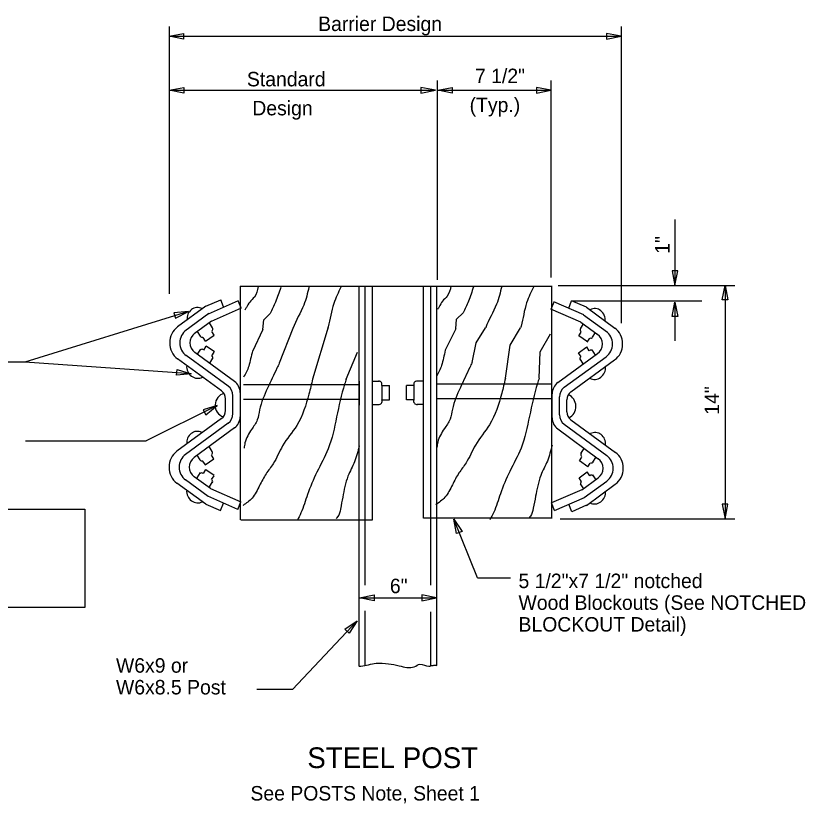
# Model space of a CAD drawing. Extents: x -0.7 to 88.8, y -25.9 to 22.
# Drawn here: x 69.51 to 77.13, y -13.93 to -6.32 of the extents above; entities that cross this region are included whole.
import ezdxf

# ---------------------------------------------------------------- set-up
doc = ezdxf.new("R2010")
doc.units = 0
doc.layers.add('Default', color=7, linetype='Continuous')

msp = doc.modelspace()

# ---------------------------------------------------------------- linework, layer by layer
at = {"layer": 'Default'}
for p, q in [((70.9916, -6.4238), (70.9917, -9.0079)), ((75.3554, -6.4238), (75.3554, -9.2896)), ((70.9896, -6.5183), (75.3554, -6.5183)), ((73.58, -6.9458), (73.58, -8.8721)), ((74.6788, -6.9458), (74.6788, -8.8479)), ((70.9913, -7.0403), (71.5695, -7.0403)), ((71.5695, -7.0403), (73.5629, -7.0403)), ((73.5856, -7.0403), (73.9534, -7.0403)), ((73.9534, -7.0403), (74.6788, -7.0403)), ((75.8756, -8.2897), (75.8756, -8.9251)), ((71.6781, -8.9328), (74.6891, -8.9328)), ((71.6781, -8.9328), (71.6781, -11.1893)), ((72.8268, -11.1891), (72.8268, -8.9399)), ((72.8835, -11.1891), (72.8835, -8.9399)), ((72.9543, -11.1891), (72.9543, -8.9399)), ((73.4472, -11.1748), (73.4472, -8.9353)), ((73.5181, -11.1748), (73.5181, -8.9353)), ((73.5747, -11.1748), (73.5747, -8.9353)), ((74.6848, -8.9328), (74.6848, -11.1749)), ((74.7482, -8.9251), (76.4542, -8.9251)), ((76.3597, -8.9251), (76.3597, -9.6308)), ((71.3455, -9.1263), (71.4894, -9.0634)), ((71.5169, -9.1336), (71.4899, -9.0643)), ((71.3457, -9.1266), (71.0728, -9.3266)), ((71.3702, -9.1993), (71.6596, -9.0729)), ((71.3994, -9.2698), (71.689, -9.1436)), ((71.6858, -9.1431), (71.6588, -9.0739)), ((74.681, -9.1539), (74.708, -9.0846)), ((74.9966, -9.2101), (74.7071, -9.0838)), ((74.85, -9.1443), (74.877, -9.0751)), ((74.8774, -9.0743), (76.1356, -9.0743)), ((75.0214, -9.1371), (74.8774, -9.0743)), ((75.0211, -9.1374), (75.294, -9.3374)), ((75.8756, -9.087), (75.8756, -9.462)), ((71.3727, -9.1978), (71.1427, -9.3664)), ((71.9674, -9.1984), (71.9051, -9.2591)), ((73.8296, -9.1913), (73.7673, -9.2519)), ((74.9674, -9.2806), (74.6779, -9.1543)), ((74.9941, -9.2086), (75.2241, -9.3773)), ((71.3986, -9.2703), (71.2319, -9.3924)), ((71.41, -9.3349), (71.3798, -9.2876)), ((71.8969, -9.3531), (71.9051, -9.2591)), ((73.7591, -9.3459), (73.7673, -9.2519)), ((74.9626, -9.3436), (74.9927, -9.2963)), ((74.9683, -9.2811), (75.135, -9.4033)), ((71.2942, -9.4174), (71.2651, -9.3718)), ((71.4251, -9.4049), (71.4025, -9.3694)), ((71.8969, -9.3531), (71.7947, -9.5639)), ((72.1865, -9.3413), (72.0544, -9.6771)), ((72.5267, -9.3281), (72.3761, -9.8301)), ((73.7591, -9.3459), (73.6581, -9.5521)), ((71.3429, -9.4639), (71.3198, -9.4276)), ((71.3427, -9.4634), (71.4253, -9.4049)), ((75.0299, -9.4721), (74.9473, -9.4134)), ((74.9474, -9.4136), (74.9701, -9.3781)), ((75.0296, -9.4724), (75.0528, -9.4363)), ((75.0784, -9.4261), (75.1075, -9.3804)), ((71.3245, -9.5498), (71.3491, -9.5111)), ((71.4276, -9.5688), (71.349, -9.5113)), ((74.945, -9.5774), (75.0236, -9.5199)), ((75.0481, -9.5584), (75.0234, -9.5198)), ((71.5596, -9.8986), (71.1556, -9.6041)), ((71.6227, -9.8536), (71.2381, -9.5733)), ((71.2646, -9.5901), (71.2962, -9.5401)), ((71.4035, -9.6073), (71.4273, -9.5698)), ((72.7019, -9.8301), (72.8103, -9.5713)), ((74.7441, -9.8643), (75.1287, -9.5839)), ((74.9691, -9.6159), (74.9452, -9.5783)), ((75.1081, -9.5988), (75.0763, -9.5488)), ((71.2038, -9.7793), (69.5972, -9.6669)), ((71.4964, -9.9436), (71.0732, -9.6351)), ((71.3826, -9.6761), (71.4136, -9.6276)), ((74.8072, -9.9093), (75.2111, -9.6149)), ((74.8705, -9.9543), (75.2936, -9.6459)), ((74.99, -9.6848), (74.9591, -9.6361)), ((76.3597, -9.6308), (76.3597, -11.1798)), ((72.8223, -9.8877), (71.7103, -9.8877)), ((72.8282, -10.0842), (72.8282, -9.8517)), ((72.9528, -9.8504), (73.0212, -9.8504)), ((73.0451, -9.8912), (73.1177, -9.8912)), ((73.0451, -9.8912), (73.0461, -10.0314)), ((73.1177, -10.0314), (73.1177, -9.8912)), ((73.2824, -10.0314), (73.2824, -9.8922)), ((73.3551, -9.8912), (73.2834, -9.8912)), ((73.3551, -9.8912), (73.3541, -10.0314)), ((73.4473, -9.8504), (73.379, -9.8504)), ((74.6845, -9.8807), (73.5726, -9.8807)), ((74.6905, -10.2049), (74.6905, -9.9724)), ((71.5347, -10.1351), (71.5347, -10.0208)), ((71.6056, -10.1644), (71.6056, -9.9913)), ((72.8223, -10.0279), (71.71, -10.0279)), ((73.0461, -10.0314), (73.1177, -10.0314)), ((73.3541, -10.0314), (73.2824, -10.0314)), ((74.6845, -10.0209), (73.5721, -10.0209)), ((74.7612, -10.1753), (74.7612, -10.0021)), ((74.8321, -10.1459), (74.8321, -10.0314)), ((71.455, -10.0859), (70.7698, -10.4277)), ((71.6056, -10.0833), (71.6056, -10.0724)), ((72.9528, -10.0749), (73.0124, -10.0749)), ((73.4473, -10.0749), (73.3877, -10.0749)), ((74.7612, -10.0939), (74.7612, -10.0833)), ((71.4966, -10.2123), (71.0662, -10.5276)), ((71.5597, -10.2569), (71.1486, -10.5584)), ((74.8071, -10.2678), (75.2181, -10.5693)), ((74.8702, -10.2229), (75.3006, -10.5384)), ((71.6231, -10.3019), (71.2313, -10.5891)), ((74.7438, -10.3128), (75.1356, -10.5999)), ((69.6048, -10.4277), (70.7698, -10.4277)), ((71.4076, -10.5296), (71.3775, -10.4823)), ((74.9683, -10.5501), (74.9984, -10.5028)), ((71.2918, -10.6123), (71.2627, -10.5666)), ((71.4228, -10.5998), (71.4001, -10.5643)), ((74.9531, -10.6203), (74.9757, -10.5848)), ((75.0841, -10.6328), (75.1131, -10.5871)), ((71.3406, -10.6586), (71.3174, -10.6223)), ((71.3404, -10.6583), (71.4229, -10.5996)), ((75.0356, -10.6788), (74.953, -10.6201)), ((75.0353, -10.6791), (75.0585, -10.6428)), ((71.2621, -10.7848), (71.2939, -10.7348)), ((71.3221, -10.7444), (71.3468, -10.7058)), ((71.4253, -10.7634), (71.3466, -10.7059)), ((74.9506, -10.7839), (75.0293, -10.7264)), ((75.0537, -10.7649), (75.0291, -10.7263)), ((71.3668, -10.9639), (71.1491, -10.8053)), ((71.3889, -10.8889), (71.2315, -10.7743)), ((71.3802, -10.8709), (71.4112, -10.8223)), ((71.4011, -10.8019), (71.425, -10.7644)), ((74.9748, -10.8224), (74.9509, -10.7849)), ((74.9779, -10.8998), (75.1353, -10.7851)), ((75, -10.9748), (75.2178, -10.8161)), ((75.1137, -10.8053), (75.082, -10.7553)), ((71.3461, -11.0399), (71.0666, -10.8363)), ((71.3889, -10.8886), (71.6826, -11.0166)), ((74.9779, -10.8994), (74.6842, -11.0274)), ((74.9956, -10.8914), (74.9647, -10.8428)), ((75.0208, -11.0508), (75.3002, -10.8471)), ((71.6546, -11.0898), (71.3652, -10.9634)), ((74.7121, -11.1006), (75.0016, -10.9743)), ((71.3437, -11.0391), (71.4877, -11.1019)), ((71.4868, -11.1016), (71.5151, -11.0289)), ((71.6538, -11.0898), (71.6826, -11.0161)), ((74.713, -11.1006), (74.6843, -11.0269)), ((74.88, -11.1123), (74.8516, -11.0398)), ((75.0231, -11.0499), (74.8791, -11.1126)), ((71.6831, -11.1891), (72.9543, -11.1891)), ((72.8268, -12.6013), (72.8268, -11.1891)), ((72.8835, -11.8228), (72.8835, -11.1891)), ((74.6891, -11.1748), (73.4472, -11.1748)), ((73.5181, -11.8206), (73.5181, -11.1748)), ((73.5747, -12.5966), (73.5747, -11.1748)), ((73.9682, -11.7506), (73.7412, -11.1828)), ((74.7661, -11.1798), (76.4542, -11.1798)), ((73.9682, -11.7506), (74.2891, -11.7506)), ((72.8268, -11.9441), (73.572, -11.9441)), ((72.8305, -11.9441), (73.018, -11.9441)), ((72.8835, -12.6013), (72.8835, -12.0703)), ((73.5181, -12.5966), (73.5181, -12.0789)), ((72.1817, -12.8304), (72.8061, -12.1656)), ((72.1817, -12.8304), (71.839, -12.8304))]:
    msp.add_line(p, q, dxfattribs=at)
for points in [[(71.1296, -6.5463), (70.9896, -6.5183), (71.1296, -6.4903)], [(75.2154, -6.5463), (75.3554, -6.5183), (75.2154, -6.4903)], [(71.1313, -7.0683), (70.9913, -7.0403), (71.1313, -7.0123)], [(73.4229, -7.0683), (73.5629, -7.0403), (73.4229, -7.0123)], [(73.7256, -7.0683), (73.5856, -7.0403), (73.7256, -7.0123)], [(74.5388, -7.0683), (74.6788, -7.0403), (74.5388, -7.0123)], [(75.8476, -8.7851), (75.8756, -8.9251), (75.9036, -8.7851)], [(76.3317, -9.0651), (76.3597, -8.9251), (76.3877, -9.0651)], [(75.8476, -9.227), (75.8756, -9.087), (75.9036, -9.227)], [(71.0511, -9.2431), (71.1779, -9.1776), (71.0356, -9.1893)], [(71.0675, -9.7368), (71.2038, -9.7793), (71.0617, -9.7925)], [(71.3445, -10.1764), (71.455, -10.0859), (71.3183, -10.1269)], [(76.3317, -11.0398), (76.3597, -11.1798), (76.3877, -11.0398)], [(67.3933, -11.0881), (70.1781, -11.0881), (70.1781, -12.0369), (67.3933, -12.0369)], [(73.7677, -11.3231), (73.7412, -11.1828), (73.8196, -11.3021)], [(72.9705, -11.9721), (72.8305, -11.9441), (72.9705, -11.9161)], [(73.432, -11.9721), (73.572, -11.9441), (73.432, -11.9161)], [(72.6887, -12.2469), (72.8061, -12.1656), (72.729, -12.2858)]]:
    msp.add_lwpolyline(points, close=True, dxfattribs=at)
for points in [[(71.1779, -9.1776), (69.5972, -9.6669), (69.3465, -9.6669)], [(73.9166, -9.6699), (73.9556, -9.4809), (74.0477, -9.3369)], [(74.2383, -9.8231), (74.2833, -9.5034), (74.3847, -9.3369)], [(74.5641, -9.8231), (74.5746, -9.5678), (74.6726, -9.3943)]]:
    msp.add_lwpolyline(points, dxfattribs=at)
for centre, major_axis, start_param, end_param in [((71.2654, -9.2456), (0, -0.1065), 2.687211, 4.851441), ((75.1014, -9.2564), (0, -0.1065), 1.431744, 3.595974), ((71.1736, -9.4807), (0, -0.1875), 3.747084, 5.680264), ((71.236, -9.4806), (0, -0.15), 3.747137, 5.680324), ((71.3941, -9.3474), (0, 0.0198), 3.70437, 5.352473), ((74.9785, -9.356), (0, 0.0198), 0.930712, 2.578815), ((75.1309, -9.4914), (0, -0.15), 0.602861, 2.536048), ((75.1932, -9.4915), (0, -0.1875), 0.602921, 2.536101), ((71.2983, -9.4805), (0, -0.1125), 3.747102, 5.680297), ((71.307, -9.4068), (0, -0.0195), 5.247458, 6.879592), ((75.0655, -9.4154), (0, -0.0195), 5.686779, 7.318912), ((75.0685, -9.4913), (0, -0.1125), 0.602888, 2.536083), ((71.3087, -9.5633), (0, 0.021), 5.452301, 7.118326), ((75.0639, -9.5719), (0, 0.021), 5.448045, 7.11407), ((71.3944, -9.6258), (0, 0.021), 4.196406, 5.73538), ((74.9782, -9.6344), (0, 0.021), 0.547805, 2.086779), ((71.2686, -9.7081), (0, -0.115), 4.640651, 6.714317), ((75.0982, -9.7189), (0, -0.115), 5.852054, 7.925719), ((71.4993, -9.9912), (0, 0.1125), 4.712389, 5.68034), ((71.5524, -9.9616), (0, 0.1312), 4.712389, 5.680267), ((73.0196, -9.8799), (0, -0.0298), 2.729343, 3.43401), ((73.0185, -9.8807), (0, 0.03), 4.35702, 6.237266), ((73.0196, -9.8799), (0, -0.0298), 1.431351, 1.439211), ((73.3817, -9.8807), (0, 0.03), 0.045919, 1.926166), ((73.3806, -9.8799), (0, -0.0298), 4.843974, 4.851834), ((73.3806, -9.8799), (0, -0.0298), 2.849176, 3.553842), ((74.8144, -9.9724), (0, 0.1312), 0.602918, 1.570796), ((74.8675, -10.002), (0, 0.1125), 0.602846, 1.570796), ((71.5455, -10.0833), (0, -0.1171), 3.363241, 5.976631), ((71.4462, -10.0208), (0, 0.0937), 4.712389, 5.680377), ((74.9206, -10.0315), (0, 0.0937), 0.602808, 1.570796), ((74.8067, -10.0945), (0, -0.1192), 0.40519, 2.779828), ((73.0174, -10.0431), (0, -0.0326), 6.093782, 8.224205), ((73.3828, -10.0431), (0, -0.0326), 4.342165, 6.472589), ((71.4462, -10.1351), (0, -0.0937), 0.605563, 1.570796), ((71.4993, -10.1645), (0, -0.1125), 0.605651, 1.570796), ((71.5524, -10.1941), (0, -0.1312), 0.605566, 1.570796), ((74.8144, -10.2049), (0, -0.1312), 4.712389, 5.677619), ((74.8675, -10.1753), (0, -0.1125), 4.712389, 5.677535), ((74.9206, -10.1459), (0, -0.0937), 4.712389, 5.677623), ((71.2624, -10.4425), (0, -0.1065), 2.687211, 4.851441), ((75.1044, -10.4533), (0, -0.1065), 1.431744, 3.595974), ((71.167, -10.6818), (0, -0.1875), 3.747091, 5.68028), ((71.2293, -10.6817), (0, -0.15), 3.747115, 5.680355), ((71.2917, -10.6816), (0, -0.1125), 3.747102, 5.680258), ((71.3917, -10.5421), (0, 0.0198), 3.70437, 5.352473), ((74.9842, -10.5626), (0, 0.0198), 0.930712, 2.578815), ((75.1375, -10.6925), (0, -0.15), 0.602831, 2.53607), ((75.1998, -10.6926), (0, -0.1875), 0.602905, 2.536094), ((71.3047, -10.6016), (0, -0.0195), 5.247458, 6.879592), ((75.0712, -10.6221), (0, -0.0195), 5.686779, 7.318912), ((75.0751, -10.6924), (0, -0.1125), 0.602927, 2.536083), ((71.3064, -10.758), (0, 0.021), 5.452301, 7.118326), ((71.392, -10.8205), (0, 0.021), 4.196406, 5.73538), ((74.9839, -10.841), (0, 0.021), 0.547805, 2.086779), ((75.0695, -10.7785), (0, 0.021), 5.448045, 7.11407), ((71.2686, -10.9114), (0, -0.115), 4.640651, 6.714317), ((75.0982, -10.9222), (0, -0.115), 5.852054, 7.925719)]:
    msp.add_ellipse(centre, major_axis=major_axis, ratio=0.944544, start_param=start_param, end_param=end_param, dxfattribs=at)
for points in [[(71.8506, -8.9371), (71.8142, -9.0379), (71.7688, -9.0861), (71.7371, -9.1389), (71.7208, -9.1648)], [(72.0686, -8.9466), (72.0186, -9.0861), (71.9674, -9.1984)], [(72.341, -8.9418), (72.2911, -9.1149), (72.1866, -9.3409), (72.1855, -9.3441)], [(72.6497, -8.9418), (72.5816, -9.1004), (72.5271, -9.3264), (72.5225, -9.3441)], [(73.7128, -8.9299), (73.6765, -9.0308), (73.631, -9.0789), (73.5993, -9.1318), (73.5831, -9.1576)], [(73.9307, -8.9394), (73.8808, -9.0789), (73.8296, -9.1913)], [(74.2032, -8.9346), (74.1532, -9.1078), (74.0488, -9.3338), (74.0477, -9.3369)], [(74.512, -8.9346), (74.4439, -9.0933), (74.3894, -9.3193), (74.3847, -9.3369)], [(71.7959, -9.5593), (71.778, -9.6341), (71.7597, -9.7063), (71.7098, -9.8119)], [(73.6581, -9.5521), (73.6401, -9.6269), (73.622, -9.6991), (73.572, -9.8049)], [(72.0544, -9.6771), (72.0322, -9.7254), (71.9413, -9.9178), (71.8642, -10.1293), (71.8416, -10.2254), (71.7871, -10.3168), (71.7235, -10.4464), (71.7143, -10.4994)], [(73.9166, -9.6699), (73.8944, -9.7183), (73.8036, -9.9106), (73.7264, -10.1221), (73.7037, -10.2183), (73.6492, -10.3096), (73.5856, -10.4394), (73.5766, -10.4923)], [(72.3761, -9.8301), (72.341, -9.9754), (72.223, -10.2783), (72.0867, -10.4754), (71.9958, -10.6484), (71.9277, -10.7446), (71.8642, -10.8599), (71.7916, -10.9801), (71.7052, -11.0523)], [(72.7019, -9.8301), (72.6861, -9.8793), (72.6088, -10.1966), (72.5271, -10.5043), (72.4181, -10.7301), (72.3273, -10.9466), (72.2637, -11.1244), (72.2275, -11.1964)], [(74.2383, -9.8231), (74.2032, -9.9683), (74.0851, -10.2711), (73.9489, -10.4683), (73.8581, -10.6413), (73.79, -10.7374), (73.7264, -10.8528), (73.6538, -10.9729), (73.5675, -11.0451)], [(74.5641, -9.8231), (74.5483, -9.8721), (74.4711, -10.1894), (74.3894, -10.4971), (74.2804, -10.7229), (74.1896, -10.9394), (74.126, -11.1173), (74.0897, -11.1893)], [(72.8268, -10.4754), (72.7815, -10.6291), (72.7178, -10.7686), (72.668, -10.9706), (72.6452, -11.0859), (72.618, -11.1629), (72.6043, -11.1773)], [(74.6891, -10.4683), (74.6437, -10.6221), (74.5801, -10.7614), (74.5301, -10.9634), (74.5074, -11.0788), (74.4802, -11.1558), (74.4666, -11.1701)], [(72.8239, -12.6036), (72.8426, -12.6029), (72.9908, -12.5761), (73.1088, -12.5809), (73.2133, -12.6001), (73.3586, -12.6098), (73.4131, -12.5858), (73.4994, -12.6049), (73.5393, -12.5966), (73.5747, -12.5966)]]:
    msp.add_spline(points, degree=3, dxfattribs=at)

# ---------------------------------------------------------------- texts
for s, height, p in [('Barrier Design', 0.14, (72.4302, -6.4681)), ('Standard', 0.14, (71.7421, -7.0026)), (' 7 1/2"', 0.14, (73.8928, -6.9716)), (' Design', 0.14, (71.7421, -7.2826)), ('(Typ.)', 0.14, (73.8928, -7.2516)), ('5 1/2"x7 1/2" notched', 0.14, (74.3652, -11.8501)), ('6" ', 0.14, (73.123, -11.8992)), ('Wood Blockouts (See NOTCHED', 0.14, (74.3652, -12.0601)), ('BLOCKOUT Detail)', 0.14, (74.3652, -12.2701)), ('W6x9 or', 0.14, (70.4775, -12.6674)), ('W6x8.5 Post', 0.14, (70.4775, -12.8774)), ('STEEL POST', 0.2, (72.3253, -13.5891)), ('See POSTS Note, Sheet 1', 0.14, (71.7761, -13.9024))]:
    msp.add_text(s, height=height, dxfattribs=at).set_placement(p)
for s, p in [('1" ', (75.8245, -8.6195)), ('14" ', (76.3023, -10.1749))]:
    msp.add_text(s, height=0.14, rotation=90, dxfattribs=at).set_placement(p)

doc.saveas('drawing.dxf')
